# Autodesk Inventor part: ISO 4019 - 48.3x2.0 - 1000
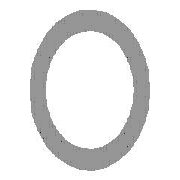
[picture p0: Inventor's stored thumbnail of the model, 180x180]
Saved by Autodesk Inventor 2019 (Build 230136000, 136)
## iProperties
_CCFamilyMember: 14
_CCFamilyDisplayName: ISO 4019 (Profils creux circulaires - Formés à froid) - Aciers de construction - Coupes creuses profilées formées à froid, soudées — ISO 4019 (Profils creux cir
_FrameMemberDoc: Frame Member File
_Version: 15.0.0
_GetPNFromCC: 1
Created: 2018-01
Part Number: ISO 4019 - 48.3x2.0 - 1000
Material: Acier, doux
Description: Aciers de construction - Coupes creuses profilées formées à froid, soudées
Document SubType Name: Modeling
Standard: ISO
Designer: Fabian Perrée
Standard Revision: Second edition 2001-09-01
Standards Organization: ISO
Language: fr-FR
Size Designation: 48.3x2.0
Categories: <MemberInstance><Categories><Category DisplayName="Profilés" InternalName="089c4875-fa83-4c05-b084-43b9cc11f5ed" Mnemonic="GRDR"><CategoryParameter DisplayName=
Stock Number: 48.3x2.0
Density: 7.85 g/cm^3
Appearance: Semi-poli
Mass: 2169.28 g
Surface Area: 2784.05 cm^2
Volume: 276.341 cm^3
IsCustomPart: 1
G_L: 1000,000 mm
G_W: 48,300 mm
G_H: 48,300 mm
+B165CBF4-667B-4DA3-AF45-A5B7E1368CCB+DETAILDECOUPE1: Grugeage
+8F40B860-9FE4-4B34-9FFF-D4066A5AD6B0+DETAILDECOUPE2: Grugeage
Author: Fabian Perrée
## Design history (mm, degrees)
node "Plan de départ"
node "Plan de fin"
sketch "Esquisse"
  geometry: C1 r 22.15 at (0, 0); C2 r 24.15 at (0, 0); 2 further points
  constraints: 3 coincident, 2 centre point
  dimensions: "d0" = 48.3 diameter of C2 (= G_H); "d1" = 2 radial gap between concentric circles of C2 C1 (= G_T)
extrude "Corps" new body sketch "Esquisse" stored distance "d2" = 1000 (= G_L); taper "d3" = 0 deg
node "Driven Length"
  sketch "Sketch3"
    geometry: L1 (0, 0)-(10, 0) reference
    constraints: 2 end point, 1 horizontal
  workplane "Work Plane3"
  sketch "Sketch4"
    geometry: L1 (-2, 0)-(12, 0) reference; L2 (-2, 1000)-(12, 1000) reference
    dimensions: "d7" = 1000 distance between parallel lines of L1 L2 (derived)
body "Solid1"
feature "Sculpter1"
feature "Combiner1"
feature "Sculpter3"
feature "Combiner3"
body "Srf20"
body "Srf21"
node "Solide8"
body "Srf23"
body "Srf24"
node "Solide9"
feature "Surface1"
body "Srf19"
feature "Carreau délimité13" dims "d32" = 5, "d33" = 0
feature "Carreau délimité14" dims "d34" = 5, "d35" = 0
feature "Surface3"
body "Srf22"
feature "Carreau délimité15" dims "d36" = 5, "d37" = 0
feature "Carreau délimité16" dims "d38" = 5, "d39" = 0
other parameters: "G_H" = 48.3 [user parameter; used in 1 equation term], "G_T" = 2 [user parameter; used in 1 equation term], "G_L" = 1000 (= d7) [user parameter; used in 1 equation term], "G_OFFSET_START" = 0 [user parameter; used in 1 equation term], "G_OFFSET_END" = 0 [user parameter; used in 1 equation term], "d4" = 0 (computed from G_OFFSET_START), "d6" = 90 deg, "MAS" = 0.228 [user parameter]
